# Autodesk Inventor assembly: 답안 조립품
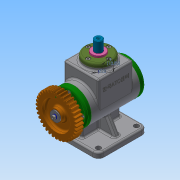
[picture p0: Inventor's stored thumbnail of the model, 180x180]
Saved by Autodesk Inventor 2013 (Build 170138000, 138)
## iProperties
Created: 2019-01
Part Number: 답안 조립품
Document SubType Name: Assembly
Designer: Administrator
Mass: 1743.42 g
Surface Area: 1517.22 cm^2
Volume: 491.998 cm^3
Density: 3.54355 g/cm^3
Author: Administrator
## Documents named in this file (18)
- C:\Users\Administrator\Desktop\390107V1043\답안 조립품.iam
- C:\Users\Administrator\Desktop\390107V1043\본체.ipt
- C:\Users\Administrator\Desktop\390107V1043\베어링 6203.ipt
- C:\Users\Administrator\Desktop\390107V1043\편심축.ipt
- C:\Users\Administrator\Desktop\390107V1043\앞커버.ipt
- C:\Users\Administrator\Desktop\390107V1043\뒤커버.ipt
- C:\Users\Administrator\Desktop\390107V1043\상부커버.ipt
- C:\Users\Administrator\Desktop\390107V1043\볼트 M4.ipt
- C:\Users\Administrator\Desktop\390107V1043\오일 실 17 30 5.ipt
- C:\Users\Administrator\Desktop\390107V1043\키 4x4x12.ipt
- C:\Users\Administrator\Desktop\390107V1043\스퍼기어.ipt
- C:\Users\Administrator\Desktop\390107V1043\평와셔.ipt
- C:\Users\Administrator\Desktop\390107V1043\스프링와셔.ipt
- C:\Users\Administrator\Desktop\390107V1043\부시.ipt
- C:\Users\Administrator\Desktop\390107V1043\멈춤링.ipt
- C:\Users\Administrator\Desktop\390107V1043\슬라이더.ipt
- C:\Users\Administrator\Desktop\390107V1043\스프링조립용 와셔.ipt
- C:\Users\Administrator\Desktop\390107V1043\가변스프링.ipt
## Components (1 placed, 1 different names)
1. 가변스프링:1
